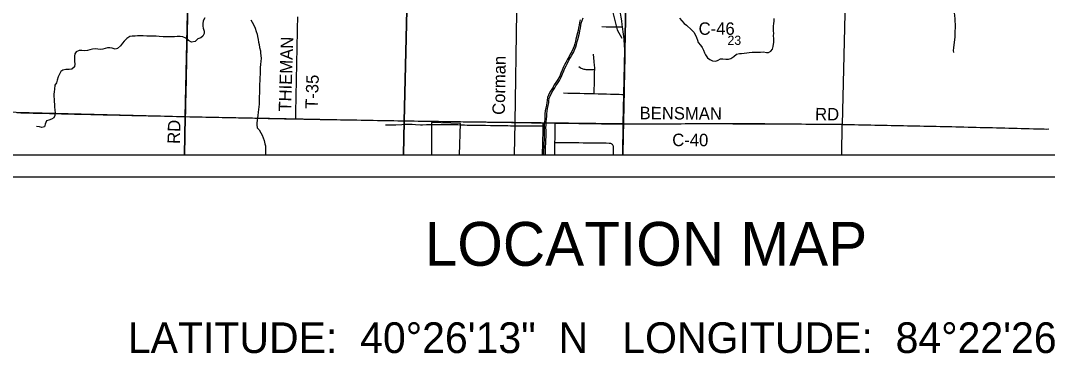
# Model space of a CAD drawing. Extents: x -11.1 to 34, y -3.9 to 22.
# Drawn here: x 2.581 to 7.271, y 13.194 to 14.712 of the extents above; entities that cross this region are included whole.
import ezdxf

# ---------------------------------------------------------------- set-up
doc = ezdxf.new("R2010")
doc.units = 0
for name, color, linetype in [('GM_X_City_Street', 7, 'Continuous'), ('GM_X_Corporation', 7, 'Continuous'), ('GM_X_County_Road', 7, 'Continuous'), ('GM_X_County_Road_Text', 7, 'Continuous'), ('GM_X_Minor_River', 7, 'Continuous'), ('GM_X_Rail_Line', 7, 'Continuous'), ('GM_X_Rail_Line_Text', 7, 'Continuous'), ('GM_X_Section_Text', 7, 'Continuous'), ('GM_X_State_Route', 7, 'Continuous'), ('GM_X_Township_Road', 7, 'Continuous'), ('GM_X_Township_Road_Text', 7, 'Continuous'), ('SH_Data', 7, 'Continuous'), ('SH_Text', 7, 'Continuous')]:
    doc.layers.add(name, color=color, linetype=linetype)

msp = doc.modelspace()

# ---------------------------------------------------------------- linework, layer by layer
at = {"layer": 'GM_X_City_Street'}
for points in [[(5.2007, 14.3789), (5.201, 14.3896), (5.2012, 14.4003), (5.2016, 14.419), (5.2019, 14.4326), (5.2022, 14.4461), (5.2026, 14.4648), (5.2028, 14.4767), (5.2031, 14.4887), (5.2033, 14.4975), (5.2029, 14.5074), (5.2008, 14.526), (5.1989, 14.5429), (5.1971, 14.5598)], [(5.13, 14.5032), (5.1372, 14.4982), (5.1411, 14.4957), (5.1453, 14.4936), (5.1496, 14.4919), (5.1541, 14.4907), (5.1587, 14.4899), (5.1633, 14.4896), (5.1804, 14.4892), (5.1974, 14.4889), (5.2031, 14.4887)], [(5.0614, 14.3823), (5.08, 14.3818), (5.0986, 14.3814), (5.1173, 14.3809), (5.1359, 14.3805), (5.1546, 14.38), (5.1732, 14.3796), (5.187, 14.3792), (5.2007, 14.3789), (5.2194, 14.3784), (5.238, 14.378), (5.2566, 14.3775), (5.2753, 14.3771), (5.2939, 14.3766), (5.3046, 14.3764), (5.3153, 14.3761), (5.3271, 14.3758), (5.339, 14.3755)], [(5.0209, 14.1), (5.0211, 14.1144), (5.0213, 14.133), (5.0215, 14.1449), (5.0217, 14.1568), (5.0219, 14.1742), (5.0222, 14.1916), (5.0225, 14.2103), (5.0227, 14.2233), (5.0228, 14.2363), (5.023, 14.245)], [(5.0217, 14.1568), (5.0379, 14.1566), (5.0566, 14.1563), (5.0752, 14.1561), (5.0938, 14.1559), (5.1125, 14.1557), (5.1311, 14.1554), (5.1498, 14.1552), (5.1684, 14.155), (5.187, 14.1547), (5.2057, 14.1545), (5.2243, 14.1543), (5.243, 14.1541), (5.2562, 14.1539), (5.2694, 14.1537), (5.2723, 14.1535), (5.2752, 14.1527), (5.2779, 14.1516), (5.2805, 14.15), (5.2827, 14.148), (5.2846, 14.1457), (5.2861, 14.1432), (5.2872, 14.1404), (5.2879, 14.1375), (5.2881, 14.1346), (5.2879, 14.1159), (5.2877, 14.1)]]:
    msp.add_lwpolyline(points, dxfattribs=at)
at = {"layer": 'GM_X_Corporation'}
for points in [[(8.9, 20.9), (2.1, 20.9), (2.1, 14.1), (7.332, 14.1)], [(7.3508, 15.2219), (6.3599, 15.2448), (5.2769, 15.2522), (5.0169, 15.252), (4.8684, 15.2535), (4.6535, 15.2566), (4.6407, 15.2568), (4.6334, 15.2569), (4.4824, 15.2598), (4.4622, 15.2602), (3.8581, 15.2731), (3.3566, 15.2846), (3.2832, 15.2853), (3.2754, 15.2855), (3.0179, 15.2909), (2.7781, 15.2969), (2.3479, 15.3077), (2.171, 15.3082), (2.1, 15.3106), (2.1, 14.1), (7.332, 14.1)]]:
    msp.add_lwpolyline(points, dxfattribs=at)
for points in [[(2.3502, 15.3059), (3.3556, 15.2873), (3.3334, 14.2733), (2.3217, 14.2992)], [(4.3579, 15.2669), (4.3335, 14.2541), (3.3334, 14.2733), (3.3556, 15.2873)], [(5.3559, 15.2538), (5.3338, 14.242), (4.3335, 14.2541), (4.3579, 15.2669)], [(5.3559, 15.2538), (6.3578, 15.2497), (6.3333, 14.2384), (5.3338, 14.242)], [(2.3164, 14.1), (3.3293, 14.1), (3.3334, 14.2733), (2.3217, 14.2992)], [(3.3293, 14.1), (4.3306, 14.1), (4.3335, 14.2541), (3.3334, 14.2733)], [(4.3306, 14.1), (5.3318, 14.1), (5.3338, 14.242), (4.3335, 14.2541)], [(4.4578, 14.1), (4.5857, 14.1), (4.5899, 14.243), (4.4586, 14.2475)], [(5.3318, 14.1), (6.3317, 14.1), (6.3333, 14.2384), (5.3338, 14.242)]]:
    msp.add_lwpolyline(points, close=True, dxfattribs=at)
at = {"layer": 'GM_X_County_Road'}
msp.add_line((5.5243, 14.2416), (5.5272, 14.2416), dxfattribs=at)
for points in [[(4.9651, 14.1), (4.9655, 14.118), (4.966, 14.1366), (4.9665, 14.1553), (4.967, 14.1739), (4.9675, 14.1925), (4.9679, 14.2112), (4.9683, 14.2244), (4.9686, 14.2376), (4.9688, 14.2457)], [(5.336, 14.2404), (5.3547, 14.2406), (5.3733, 14.2407), (5.3919, 14.2408), (5.4106, 14.2409), (5.4217, 14.241), (5.4328, 14.241)], [(5.4328, 14.241), (5.4514, 14.2411), (5.4701, 14.2412), (5.4887, 14.2414), (5.506, 14.2415), (5.5233, 14.2416), (5.5243, 14.2416)], [(5.5272, 14.2416), (5.542, 14.2417), (5.5606, 14.2418), (5.5792, 14.2419), (5.5979, 14.242), (5.6165, 14.2421), (5.6352, 14.2422), (5.6538, 14.2423), (5.6724, 14.2425), (5.6911, 14.2426), (5.7097, 14.2427), (5.7284, 14.2428), (5.747, 14.2429), (5.7657, 14.243), (5.7843, 14.2431), (5.8029, 14.2432), (5.8171, 14.2433), (5.8312, 14.2434), (5.8499, 14.2432), (5.8685, 14.2431), (5.8872, 14.2429), (5.9058, 14.2427), (5.9244, 14.2426), (5.9431, 14.2424), (5.9617, 14.2422), (5.9804, 14.2421), (5.999, 14.2419), (6.0176, 14.2417), (6.0363, 14.2416), (6.0549, 14.2414), (6.0736, 14.2412), (6.0922, 14.2411), (6.1108, 14.2409), (6.1295, 14.2407), (6.1481, 14.2406), (6.1668, 14.2404), (6.1854, 14.2402), (6.2041, 14.2401), (6.2227, 14.2399), (6.2413, 14.2398), (6.26, 14.2396), (6.2786, 14.2394), (6.2973, 14.2393), (6.3156, 14.2391), (6.3339, 14.2389), (6.3525, 14.2385), (6.3712, 14.2382), (6.3898, 14.2378), (6.4084, 14.2374), (6.4271, 14.237), (6.4457, 14.2366), (6.4643, 14.2362), (6.483, 14.2358), (6.5016, 14.2354), (6.5202, 14.235), (6.5389, 14.2346), (6.5575, 14.2342), (6.5761, 14.2338), (6.5948, 14.2335), (6.6134, 14.2331), (6.632, 14.2327), (6.6507, 14.2323), (6.6693, 14.2319), (6.688, 14.2315), (6.7066, 14.2311), (6.7252, 14.2307), (6.7439, 14.2303), (6.7625, 14.2299), (6.7811, 14.2295), (6.7998, 14.2291), (6.8167, 14.2288), (6.8337, 14.2284), (6.8523, 14.2279), (6.871, 14.2275), (6.8896, 14.227), (6.9083, 14.2265), (6.9269, 14.2261), (6.9455, 14.2256), (6.9642, 14.2251), (6.9828, 14.2247), (7.0014, 14.2242), (7.0201, 14.2238), (7.0387, 14.2233), (7.0573, 14.2228), (7.076, 14.2223), (7.0946, 14.2219), (7.1132, 14.2214), (7.1319, 14.2209), (7.1505, 14.2205), (7.1691, 14.22), (7.1878, 14.2195), (7.2064, 14.2191), (7.225, 14.2186), (7.2437, 14.2181), (7.2553, 14.2178), (7.2669, 14.2175), (7.2764, 14.2178)]]:
    msp.add_lwpolyline(points, dxfattribs=at)
at = {"layer": 'GM_X_Minor_River'}
for points in [[(6.8454, 14.7481), (6.847, 14.7348), (6.8474, 14.72), (6.8478, 14.7074), (6.8486, 14.6964), (6.849, 14.6816), (6.8485, 14.6615), (6.8477, 14.6486), (6.8471, 14.6368), (6.846, 14.6259), (6.8441, 14.6119), (6.8431, 14.6013), (6.8416, 14.5876), (6.8405, 14.5755), (6.841, 14.566)], [(3.4226, 14.7252), (3.4155, 14.7117), (3.4133, 14.6981), (3.4138, 14.6871), (3.4159, 14.6775), (3.4193, 14.6634), (3.4191, 14.6535), (3.4143, 14.6411), (3.4042, 14.6333), (3.3912, 14.6287), (3.3781, 14.6172), (3.3613, 14.6135), (3.3489, 14.621), (3.3359, 14.6327), (3.3224, 14.6383), (3.3095, 14.6393), (3.2963, 14.6396), (3.2841, 14.6388), (3.2727, 14.6375), (3.2587, 14.6375), (3.2439, 14.6378), (3.2321, 14.6377), (3.2143, 14.64), (3.2007, 14.6411), (3.1905, 14.6413), (3.1757, 14.6409), (3.1582, 14.6409), (3.1408, 14.6421), (3.1271, 14.6428), (3.1154, 14.6423), (3.1047, 14.6418), (3.0915, 14.6417), (3.08, 14.6401), (3.0665, 14.6298), (3.0545, 14.6186), (3.0467, 14.6089), (3.0377, 14.5977), (3.0245, 14.5844), (3.0127, 14.582), (2.9992, 14.5865), (2.989, 14.5882), (2.9787, 14.5877), (2.9673, 14.5846), (2.9577, 14.5825), (2.9452, 14.5809), (2.9338, 14.5815), (2.924, 14.5829), (2.9092, 14.5825), (2.8981, 14.5793), (2.8874, 14.5765), (2.8741, 14.5745), (2.8605, 14.5756), (2.8483, 14.5763), (2.8353, 14.5701), (2.8286, 14.5604), (2.8269, 14.5494), (2.8269, 14.5361), (2.8278, 14.5255), (2.8287, 14.5144), (2.8269, 14.5012), (2.8157, 14.4904), (2.8031, 14.4896), (2.7887, 14.4884), (2.775, 14.4856), (2.765, 14.4805), (2.759, 14.4674), (2.753, 14.455), (2.7482, 14.4403), (2.7449, 14.4286), (2.7381, 14.417), (2.7366, 14.3995), (2.7344, 14.3878), (2.7338, 14.376), (2.7336, 14.3658), (2.734, 14.3532), (2.735, 14.3437), (2.7358, 14.3289), (2.7366, 14.3175), (2.7383, 14.3049), (2.7387, 14.2905), (2.7377, 14.2791), (2.7325, 14.2686), (2.7229, 14.262), (2.7099, 14.2577), (2.7003, 14.2545), (2.6939, 14.2402), (2.6906, 14.2281), (2.6791, 14.2238), (2.6679, 14.2275)], [(3.6326, 14.7162), (3.6388, 14.705), (3.645, 14.6942), (3.6522, 14.677), (3.6579, 14.6632), (3.6611, 14.6509), (3.6627, 14.6403), (3.6662, 14.6261), (3.6678, 14.6139), (3.671, 14.6028), (3.673, 14.5895), (3.6764, 14.5742), (3.6773, 14.5643), (3.679, 14.5525), (3.6794, 14.5396), (3.6788, 14.5275), (3.6765, 14.5119), (3.6755, 14.4979), (3.6748, 14.4842), (3.6737, 14.4357), (3.673, 14.4239), (3.672, 14.3787), (3.6714, 14.3689), (3.6709, 14.3468), (3.6702, 14.3317), (3.6691, 14.3195), (3.6673, 14.3059), (3.6659, 14.2949), (3.6641, 14.2794), (3.6627, 14.2688), (3.6613, 14.2563)], [(5.1374, 14.715), (5.1338, 14.7029), (5.1316, 14.6908), (5.1298, 14.6787), (5.1276, 14.6677), (5.1251, 14.6567), (5.1176, 14.628), (5.1151, 14.6182), (5.1122, 14.6058), (5.1089, 14.5948), (5.1049, 14.5847), (5.0981, 14.5711), (5.0918, 14.5584), (5.0859, 14.5483), (5.0784, 14.5355), (5.0716, 14.5216), (5.0653, 14.5104), (5.0593, 14.4987), (5.0541, 14.4863), (5.0489, 14.4724), (5.0432, 14.4581), (5.0346, 14.4435), (5.0263, 14.4304), (5.0188, 14.4188), (5.0133, 14.409), (5.005, 14.3955), (4.9987, 14.3851), (4.9923, 14.3719), (4.9872, 14.3614), (4.9857, 14.3478), (4.9848, 14.3379), (4.983, 14.3262), (4.98, 14.3137), (4.9771, 14.3001), (4.976, 14.2872), (4.9757, 14.2751), (4.9747, 14.2641), (4.9733, 14.2493), (4.9726, 14.236), (4.9723, 14.2246), (4.9728, 14.2113), (4.9729, 14.2003), (4.9729, 14.1836), (4.9722, 14.1673), (4.9715, 14.1544), (4.9702, 14.1331), (4.97, 14.1218), (4.9697, 14.1085), (4.9695, 14.1)], [(4.9779, 14.1), (4.9781, 14.1083), (4.9784, 14.1216), (4.9786, 14.1328), (4.9799, 14.1539), (4.9806, 14.1669), (4.9813, 14.1834), (4.9813, 14.2004), (4.9812, 14.2115), (4.9807, 14.2247), (4.981, 14.2357), (4.9816, 14.2487), (4.9831, 14.2633), (4.9841, 14.2746), (4.9844, 14.2868), (4.9854, 14.2989), (4.9882, 14.3118), (4.9912, 14.3246), (4.9931, 14.3369), (4.9941, 14.3469), (4.9954, 14.359), (4.9999, 14.3682), (5.0061, 14.3811), (5.0122, 14.3912), (5.0205, 14.4048), (5.026, 14.4144), (5.0334, 14.4259), (5.0417, 14.4391), (5.0508, 14.4544), (5.0567, 14.4694), (5.0619, 14.4832), (5.067, 14.4952), (5.0727, 14.5064), (5.0791, 14.5177), (5.0858, 14.5315), (5.0931, 14.544), (5.0992, 14.5544), (5.1057, 14.5674), (5.1126, 14.5812), (5.1169, 14.5921), (5.1203, 14.6036), (5.1233, 14.6162), (5.1258, 14.626), (5.1333, 14.6547), (5.1359, 14.666), (5.1381, 14.6772), (5.1399, 14.6894), (5.1419, 14.7009), (5.1454, 14.7123), (5.1502, 14.7254)], [(5.5906, 14.7228), (5.6009, 14.7107), (5.6123, 14.699), (5.622, 14.6919), (5.645, 14.6708), (5.6553, 14.6588), (5.6622, 14.6491), (5.6687, 14.6349), (5.6729, 14.6223), (5.6761, 14.6127), (5.686, 14.5996), (5.6937, 14.5891), (5.7002, 14.5779), (5.7052, 14.5653), (5.7098, 14.5553), (5.7186, 14.5429), (5.729, 14.535), (5.7417, 14.5283), (5.7565, 14.5264), (5.7665, 14.5318), (5.778, 14.5376), (5.7887, 14.538), (5.8019, 14.5369), (5.8148, 14.5362), (5.8244, 14.5394), (5.8382, 14.5478), (5.8514, 14.5584), (5.8648, 14.5619), (5.8743, 14.5628), (5.8861, 14.5636), (5.8979, 14.5652), (5.9085, 14.5664), (5.9222, 14.5676), (5.9344, 14.5676), (5.9492, 14.5676), (5.9602, 14.5681), (5.9746, 14.5696), (5.9875, 14.567), (5.9973, 14.5671), (6.007, 14.5726), (6.0148, 14.5826), (6.0185, 14.5943), (6.0206, 14.614), (6.0206, 14.6295), (6.0202, 14.6436), (6.0205, 14.6534), (6.0204, 14.6648), (6.0204, 14.6774), (6.0203, 14.688), (6.0205, 14.6975), (6.022, 14.7111), (6.023, 14.7213)], [(2.6679, 14.2275), (2.6538, 14.2286)], [(3.6613, 14.2563), (3.6607, 14.2464), (3.6604, 14.2366), (3.662, 14.2232), (3.6705, 14.2135), (3.679, 14.2008), (3.6844, 14.19), (3.6891, 14.1774), (3.6933, 14.1648), (3.6975, 14.1499), (3.6992, 14.1403), (3.7001, 14.1293), (3.7002, 14.1183), (3.7, 14.1073), (3.6993, 14.1)], [(4.9724, 14.2299), (4.9527, 14.2304), (4.9425, 14.2303), (4.9319, 14.2309), (4.9163, 14.2309), (4.9023, 14.2308), (4.8913, 14.2303), (4.8765, 14.2303), (4.8647, 14.2302), (4.831, 14.231), (4.8188, 14.2309), (4.8067, 14.2315), (4.7961, 14.2318), (4.7824, 14.2325), (4.7711, 14.2327), (4.7601, 14.2326), (4.7494, 14.2325), (4.7392, 14.2327), (4.7271, 14.2326), (4.7039, 14.2332), (4.6816, 14.2341), (4.6588, 14.2342), (4.6395, 14.2339), (4.6205, 14.2343), (4.6084, 14.235), (4.5985, 14.2356), (4.5883, 14.2358), (4.5784, 14.2361), (4.5633, 14.2361), (4.5488, 14.236), (4.5356, 14.2363), (4.525, 14.2369), (4.5105, 14.2365), (4.4988, 14.2364), (4.4889, 14.2366), (4.4749, 14.2366), (4.4578, 14.237), (4.448, 14.2368), (4.4351, 14.2364), (4.4172, 14.2357), (4.4077, 14.2359), (4.385, 14.2372), (4.3702, 14.2379), (4.36, 14.2381), (4.3467, 14.2377), (4.3364, 14.2375), (4.322, 14.2364), (4.2954, 14.2355), (4.2833, 14.2354), (4.27, 14.2353), (4.2583, 14.2352), (4.2473, 14.2358)]]:
    msp.add_lwpolyline(points, dxfattribs=at)
at = {"layer": 'GM_X_Rail_Line'}
for points in [[(4.8375, 14.1), (4.84, 14.2474), (4.8556, 15.259), (4.8714, 16.2666), (4.8783, 16.7081), (4.896, 17.8593), (4.8941, 17.9315), (4.8895, 17.9844), (4.8767, 18.0419), (4.6837, 18.6752), (4.6608, 18.751), (4.6471, 18.7984), (4.6397, 18.855), (4.6467, 19.2877), (4.6769, 20.631), (4.6804, 20.8229), (4.6818, 20.9)], [(4.878, 16.7078), (4.9266, 16.6377), (4.9294, 16.6149), (5.0609, 16.6122), (5.0598, 16.4614), (5.059, 16.2648), (5.1889, 16.2589), (5.2287, 15.8244), (5.2761, 15.2722), (5.2785, 15.2153), (5.2666, 14.9275), (5.2749, 14.792), (5.3053, 14.6694), (5.3278, 14.6319)]]:
    msp.add_lwpolyline(points, dxfattribs=at)
at = {"layer": 'GM_X_State_Route'}
for points in [[(5.3415, 14.5069), (5.3417, 14.5183), (5.342, 14.5306), (5.3418, 14.5416), (5.3417, 14.5525), (5.3413, 14.5635), (5.3409, 14.5744), (5.3404, 14.5853), (5.3398, 14.5962), (5.339, 14.6072), (5.3382, 14.6181), (5.3371, 14.629), (5.3361, 14.6399), (5.3349, 14.6507), (5.3336, 14.6616), (5.3321, 14.6724), (5.3307, 14.6833), (5.3293, 14.6925), (5.3265, 14.711), (5.3238, 14.7284), (5.3211, 14.7459)], [(5.336, 14.2404), (5.3364, 14.2591), (5.3368, 14.2777), (5.3372, 14.2963), (5.3376, 14.315), (5.338, 14.3336), (5.3384, 14.3523), (5.3387, 14.3639), (5.339, 14.3755), (5.3393, 14.3942), (5.3397, 14.4128), (5.34, 14.4314), (5.3404, 14.4501), (5.3408, 14.4687), (5.3411, 14.4873), (5.3415, 14.506), (5.3415, 14.5069)], [(2.5638, 14.2922), (2.5825, 14.2918), (2.6011, 14.2913), (2.6197, 14.2909), (2.6384, 14.2905), (2.657, 14.29), (2.6756, 14.2896), (2.6943, 14.2892), (2.7129, 14.2887), (2.7315, 14.2883), (2.7502, 14.2879), (2.7688, 14.2874), (2.7874, 14.287), (2.8061, 14.2866), (2.8171, 14.2863), (2.8282, 14.2861), (2.8469, 14.2856), (2.8655, 14.2852), (2.8841, 14.2848), (2.9028, 14.2843), (2.9214, 14.2839), (2.94, 14.2835), (2.9587, 14.283), (2.9773, 14.2826), (2.9959, 14.2822), (3.0146, 14.2817), (3.0332, 14.2813), (3.0518, 14.2809), (3.0705, 14.2804), (3.0891, 14.28), (3.1077, 14.2796), (3.1264, 14.2791), (3.145, 14.2787), (3.1636, 14.2783), (3.1823, 14.2778), (3.2009, 14.2774), (3.2196, 14.277), (3.2382, 14.2765), (3.2568, 14.2761), (3.2755, 14.2757), (3.2941, 14.2752), (3.3127, 14.2748), (3.3238, 14.2745), (3.3349, 14.2743), (3.3535, 14.2739), (3.3721, 14.2735), (3.3908, 14.2731), (3.4094, 14.2727), (3.428, 14.2723), (3.4467, 14.2719), (3.4653, 14.2715), (3.484, 14.2711), (3.5026, 14.2708), (3.5212, 14.2704), (3.5399, 14.27), (3.5585, 14.2696), (3.5771, 14.2692), (3.5958, 14.2688), (3.6144, 14.2684), (3.633, 14.268), (3.6517, 14.2676), (3.6703, 14.2672), (3.6889, 14.2668), (3.7005, 14.2666), (3.7121, 14.2663), (3.7307, 14.2659), (3.7493, 14.2655), (3.768, 14.2651), (3.7866, 14.2647), (3.8052, 14.2644), (3.8215, 14.264), (3.8378, 14.2637), (3.8564, 14.2633), (3.8751, 14.263), (3.8937, 14.2627), (3.9124, 14.2624), (3.931, 14.262), (3.9496, 14.2617), (3.9683, 14.2614), (3.9869, 14.261), (4.0056, 14.2607), (4.0242, 14.2604), (4.0428, 14.2601), (4.0615, 14.2597), (4.0801, 14.2594), (4.0988, 14.2591), (4.1174, 14.2588), (4.1361, 14.2584), (4.1547, 14.2581), (4.1733, 14.2578), (4.192, 14.2575), (4.2106, 14.2571), (4.2293, 14.2568), (4.2479, 14.2565), (4.2665, 14.2561), (4.2852, 14.2558), (4.3038, 14.2555), (4.3224, 14.2552), (4.341, 14.2548), (4.3597, 14.2546), (4.3773, 14.2543)], [(4.3773, 14.2543), (4.3783, 14.2543), (4.397, 14.254), (4.4156, 14.2538), (4.4342, 14.2535), (4.4529, 14.2532), (4.4658, 14.253)], [(4.4658, 14.253), (4.4902, 14.2527), (4.5088, 14.2524), (4.5275, 14.2521), (4.5461, 14.2519), (4.5647, 14.2516), (4.5834, 14.2513), (4.5908, 14.2512)], [(4.5908, 14.2512), (4.602, 14.2511), (4.6207, 14.2508), (4.6393, 14.2505), (4.6579, 14.2503), (4.6766, 14.25), (4.6952, 14.2497), (4.7139, 14.2494), (4.7325, 14.2492), (4.7511, 14.2489), (4.7698, 14.2486), (4.7884, 14.2484), (4.8071, 14.2481), (4.8237, 14.2478), (4.8404, 14.2476), (4.8591, 14.2473), (4.8777, 14.2471), (4.8963, 14.2468), (4.915, 14.2465), (4.9336, 14.2463), (4.9512, 14.246), (4.9688, 14.2457), (4.9788, 14.2456), (4.9888, 14.2455)], [(4.9888, 14.2455), (5.0059, 14.2452), (5.023, 14.245), (5.0274, 14.2449)], [(5.0274, 14.2449), (5.0376, 14.2448), (5.0467, 14.2446)], [(5.0467, 14.2446), (5.0478, 14.2446), (5.0664, 14.2443), (5.0783, 14.2442), (5.0891, 14.244)], [(5.0891, 14.244), (5.0901, 14.244), (5.1013, 14.2438), (5.1115, 14.2437)], [(5.1115, 14.2437), (5.1125, 14.2437), (5.1311, 14.2434), (5.145, 14.2432), (5.1579, 14.243)], [(5.1579, 14.243), (5.1589, 14.243), (5.1684, 14.2429), (5.1769, 14.2427)], [(5.1769, 14.2427), (5.1778, 14.2427), (5.1964, 14.2425), (5.2151, 14.2422), (5.2337, 14.2419), (5.2524, 14.2417), (5.271, 14.2414), (5.2896, 14.2411), (5.3083, 14.2408), (5.3222, 14.2406), (5.336, 14.2404)], [(5.3331, 14.1), (5.3334, 14.1162), (5.3338, 14.1349), (5.3342, 14.1535), (5.3346, 14.1721), (5.335, 14.1908), (5.3354, 14.2094), (5.3357, 14.2249), (5.336, 14.2404)]]:
    msp.add_lwpolyline(points, dxfattribs=at)
at = {"layer": 'GM_X_Township_Road'}
for points in [[(3.8378, 14.2637), (3.8382, 14.2823), (3.8386, 14.3009), (3.8389, 14.3196), (3.8393, 14.3382), (3.8397, 14.3568), (3.8401, 14.3755), (3.8405, 14.3941), (3.8408, 14.4127), (3.8412, 14.4314), (3.8416, 14.45), (3.842, 14.4686), (3.8424, 14.4873), (3.8427, 14.5059), (3.8431, 14.5246), (3.8435, 14.5432), (3.8439, 14.5618), (3.8443, 14.5805), (3.8447, 14.5991), (3.845, 14.6177), (3.8454, 14.6364), (3.8458, 14.655), (3.8462, 14.6736), (3.8466, 14.6923), (3.8469, 14.7109), (3.8473, 14.7295)], [(3.3299, 14.1), (3.3303, 14.1153), (3.3309, 14.1339), (3.3312, 14.1439), (3.3314, 14.154), (3.3319, 14.1705), (3.3324, 14.1869), (3.3328, 14.2016), (3.3333, 14.2202), (3.3339, 14.2389), (3.3344, 14.2566), (3.3349, 14.2743), (3.3353, 14.2929), (3.3357, 14.3116), (3.3362, 14.3302), (3.3366, 14.3488), (3.337, 14.3675), (3.3374, 14.3861), (3.3379, 14.4047), (3.3383, 14.4234), (3.3387, 14.442), (3.3392, 14.4606), (3.3396, 14.4793), (3.34, 14.4979), (3.3404, 14.5165), (3.3409, 14.5352), (3.3413, 14.5538), (3.3417, 14.5725), (3.3422, 14.5911), (3.3426, 14.6097), (3.343, 14.6284), (3.3435, 14.647), (3.3439, 14.6656), (3.3443, 14.6843), (3.3448, 14.7029), (3.3452, 14.7215)], [(5.2364, 14.6847), (5.2551, 14.6844), (5.2711, 14.6842), (5.2871, 14.6839), (5.3058, 14.6837), (5.3182, 14.6835), (5.3307, 14.6833)]]:
    msp.add_lwpolyline(points, dxfattribs=at)
at = {"layer": 'SH_Data'}
for p, q in [((2.1, 14.1), (8.9, 14.1)), ((2, 14), (9, 14))]:
    msp.add_line(p, q, dxfattribs=at)

# ---------------------------------------------------------------- texts
at = {"layer": 'GM_X_County_Road_Text'}
for s, rotation, p in [('C-46', 0, (5.6777, 14.6473)), ('BENSMAN', 359.579, (5.4081, 14.2625)), ('RD', 359.5054, (6.2095, 14.2575)), ('C-40', 359.6571, (5.5571, 14.1398))]:
    msp.add_text(s, height=0.05682, rotation=rotation, dxfattribs=at).set_placement(p)
at = {"layer": 'GM_X_Rail_Line_Text'}
msp.add_text('Corman', height=0.05663, rotation=89.0658, dxfattribs=at).set_placement((4.7926, 14.2818))
at = {"layer": 'GM_X_Section_Text'}
msp.add_text('23', height=0.04186, rotation=0, dxfattribs=at).set_placement((5.8098, 14.6015))
at = {"layer": 'GM_X_Township_Road_Text'}
for s, rotation, p in [('THIEMAN', 88.2333, (3.8164, 14.2961)), ('T-35', 87.9255, (3.938, 14.3083)), ('RD', 88.5184, (3.3087, 14.1491))]:
    msp.add_text(s, height=0.05682, rotation=rotation, dxfattribs=at).set_placement(p)
at = {"layer": 'SH_Text'}
for s, height, p in [('LOCATION MAP', 0.2, (4.4269, 13.5937)), ('LATITUDE:  40°26\'13"  N   LONGITUDE:  84°22\'26" W', 0.14, (3.071, 13.1958))]:
    msp.add_text(s, height=height, dxfattribs=at).set_placement(p)

doc.saveas('drawing.dxf')
